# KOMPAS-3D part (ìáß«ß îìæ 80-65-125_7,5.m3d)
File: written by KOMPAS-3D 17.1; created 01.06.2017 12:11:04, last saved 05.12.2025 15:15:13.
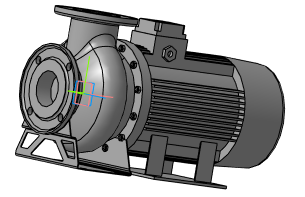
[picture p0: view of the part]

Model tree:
1. Операция без истории:7

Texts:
  ООО АДЛ ГРУПП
